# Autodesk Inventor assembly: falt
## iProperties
Created: 2004-11
Part Number: falt
Cost Center: 0,1 kg
Document SubType Name: Assembly
Designer: jwagner
Authority: 84585,93 mm^3
Manufacturer: Standard
Standards Organization: Custom
SaveDate: 2004-11-14
SaveTime: 13:09
TotalMass: 0,1 kg
TotalVolume: 84585,93 mm^3
Author: jwagner
